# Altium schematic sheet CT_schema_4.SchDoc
size 309 x 321 mm
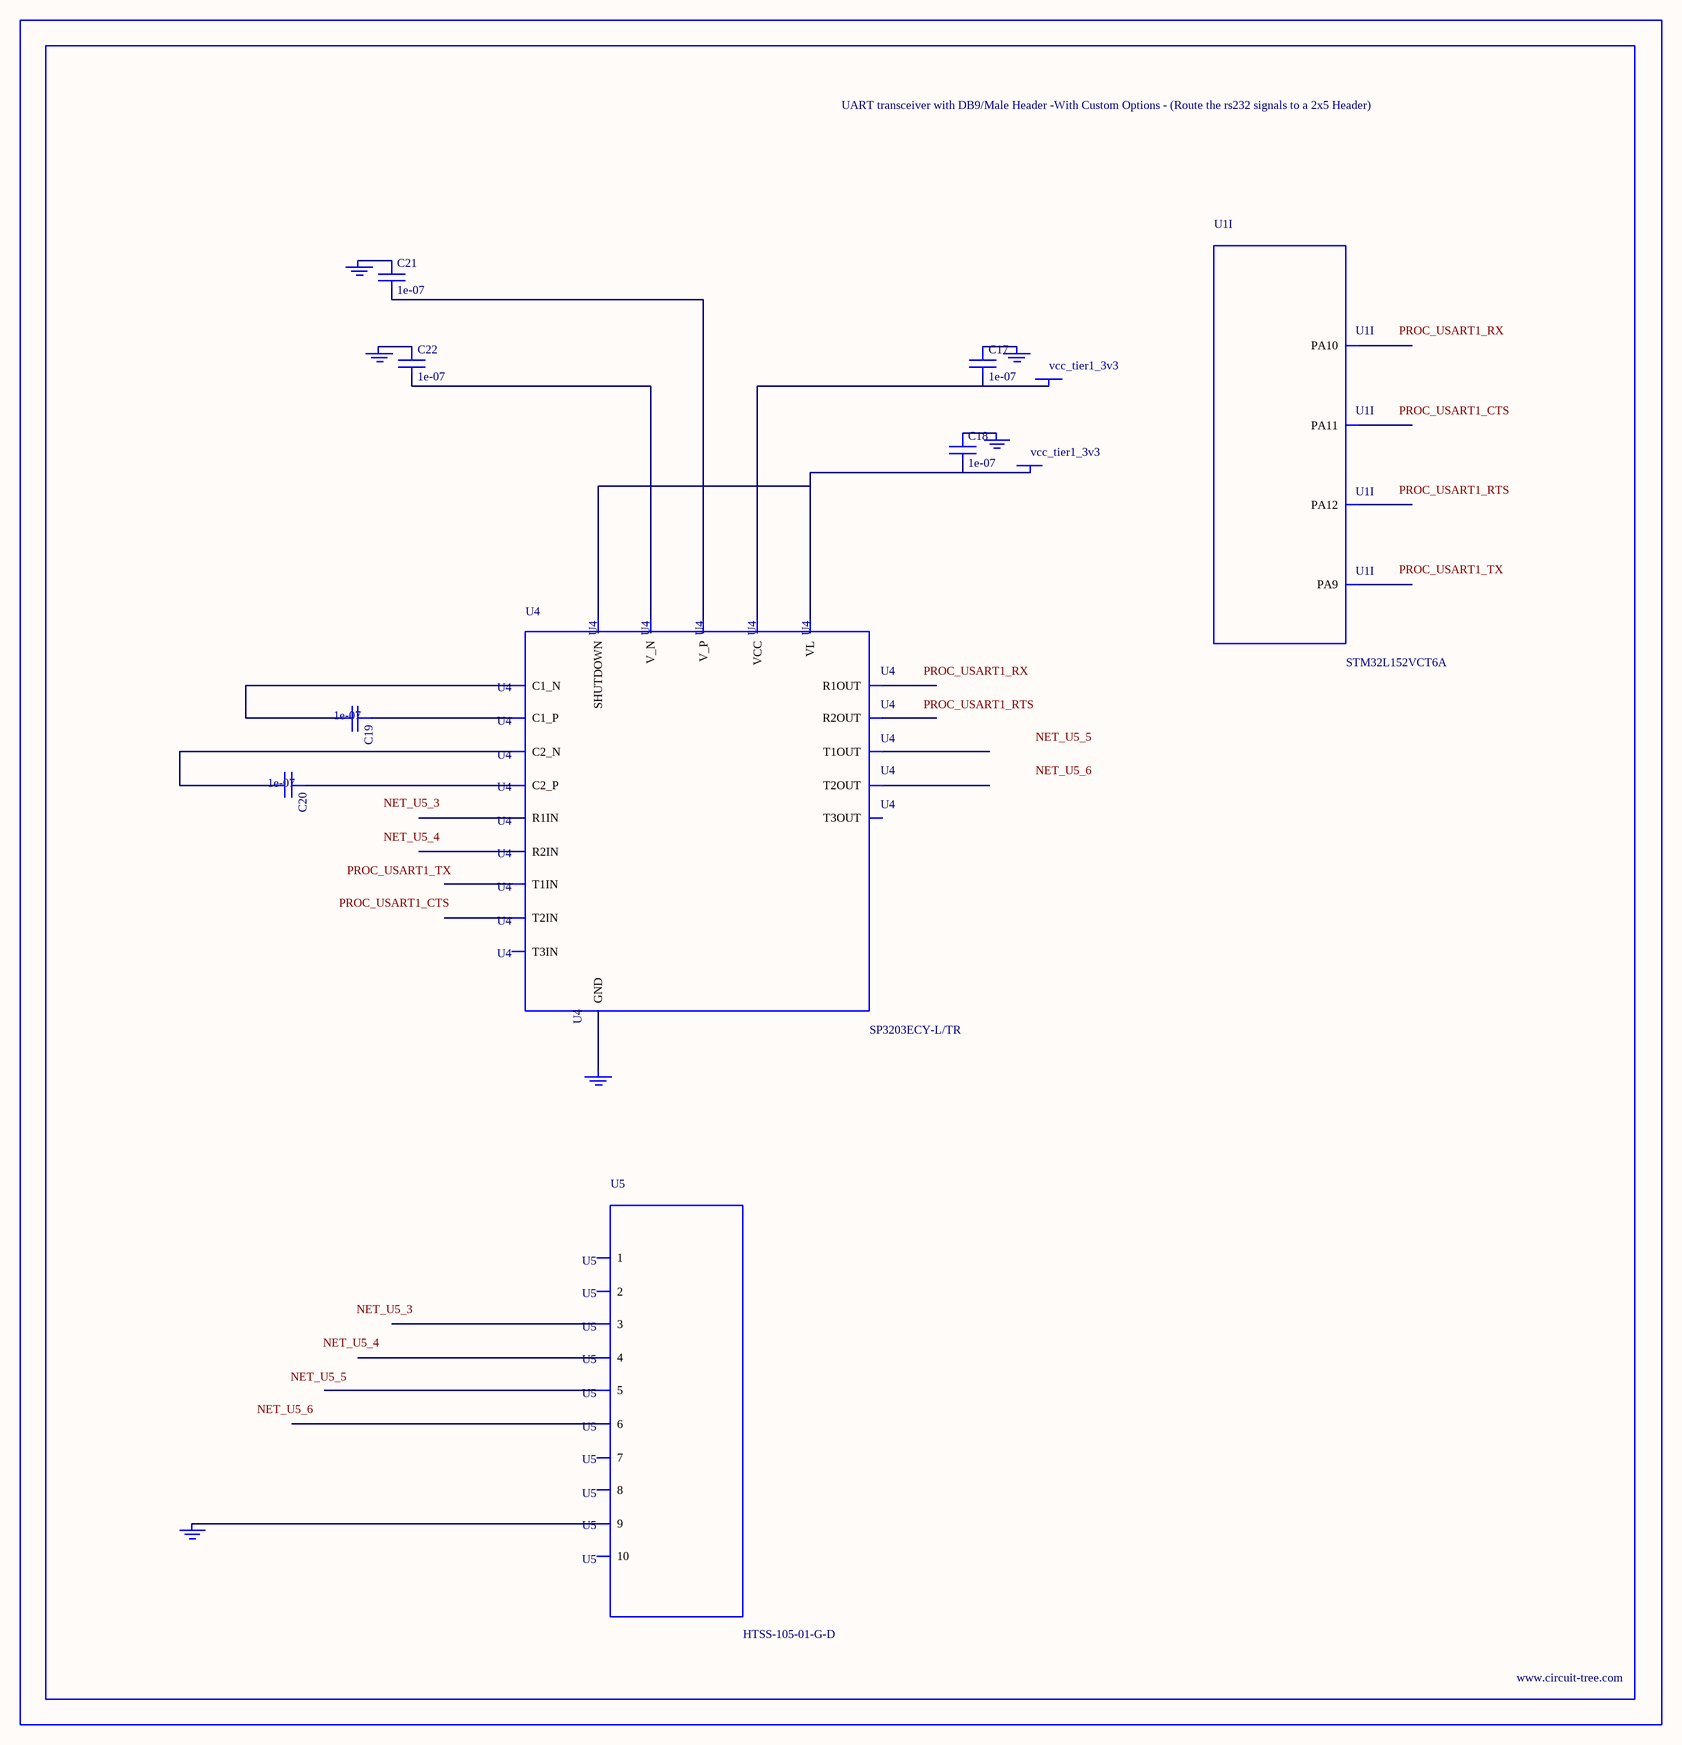
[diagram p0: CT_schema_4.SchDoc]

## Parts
BORDER3  (no value)
C17  1e-07  [C0402]
C18  1e-07  [C0402]
C19  1e-07  [C0402]
C20  1e-07  [C0402]
C21  1e-07  [C0402]
C22  1e-07  [C0402]
GND_INSTANCE_3_0  (no value)
GND_INSTANCE_3_1  (no value)
GND_INSTANCE_3_2  (no value)
GND_INSTANCE_3_3  (no value)
GND_INSTANCE_3_4  (no value)
GND_INSTANCE_3_5  (no value)
POWER_INSTANCE_3_0  vcc_tier1_3v3
POWER_INSTANCE_3_1  vcc_tier1_3v3
U1  STM32L152VCT6A  [LQFP100]  (part I of 9)
U4  SP3203ECY-L/TR  [TSSOP20-I]
U5  HTSS-105-01-G-D  [HTSS-105-01-G-D]

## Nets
NetC17_1: C17.1 GND_INSTANCE_3_3.0(GND)
NetC17_2: C17.2 POWER_INSTANCE_3_1.0(PWR) U4.19(VCC)
NetC18_1: C18.1 GND_INSTANCE_3_2.0(GND)
NetC18_2: C18.2 POWER_INSTANCE_3_0.0(PWR) U4.12(VL) U4.20(SHUTDOWN)
NetC19_1: C19.1 U4.1(C1_P)
NetC19_2: C19.2 U4.3(C1_N)
NetC20_1: C20.1 U4.4(C2_P)
NetC20_2: C20.2 U4.5(C2_N)
NetC21_1: C21.1 GND_INSTANCE_3_0.0(GND)
NetC21_2: C21.2 U4.2(V_P)
NetC22_1: C22.1 GND_INSTANCE_3_1.0(GND)
NetC22_2: C22.2 U4.6(V_N)
NetGND_INSTANCE_3_4_0: GND_INSTANCE_3_4.0(GND) U4.18(GND)
NetGND_INSTANCE_3_5_0: GND_INSTANCE_3_5.0(GND) U5.9

Not connected (* = marked no-connect by the designer): U1 68(PA9) 69(PA10) 70(PA11) 71(PA12); U4 7(T1IN) 8(T2IN) 9(T3IN) 10(R2OUT) 11(R1OUT) 13(R2IN) 14(R1IN) 15(T3OUT) 16(T2OUT) 17(T1OUT); U5 1 2 3 4 5 6 7 8 10

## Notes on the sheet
- Labels drawn without touching a wire or pin: NET_U5_3, NET_U5_4, NET_U5_5, NET_U5_6, PROC_USART1_CTS, PROC_USART1_RTS, PROC_USART1_RX, PROC_USART1_TX

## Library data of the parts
BORDER3 = BORDER_PAGE3
C17-C22 = C0402C104K3RACTU
GND_INSTANCE_3_0-GND_INSTANCE_3_5 = GND
POWER_INSTANCE_3_0 POWER_INSTANCE_3_1 = PWR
